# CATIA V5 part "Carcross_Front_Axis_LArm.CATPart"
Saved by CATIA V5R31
Part number: Carcross_Front_Axis_Larm
Bounding box of the stored display mesh (mm): x -35 to 226, y -610 to 0, z 0 to 365
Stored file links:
  R:\Din II\Pfinal\CAD\Carcross_Front_Axis_LArm.CATPart
  R:\Din II\Pfinal\CAD\Carcross_Front_Axis_HP.CATPart
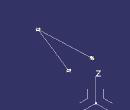
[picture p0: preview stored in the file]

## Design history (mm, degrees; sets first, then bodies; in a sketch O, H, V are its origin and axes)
AxisSystem1: origin (0, 0, 0), X (1, 0, 0), Y (0, 1, 0), Z (0, 0, 1)
Set1 "Front_Axis"
  Set2 "Left_wheel"
    Set3 "Upper_arm"
      Set4 "Upper_arm_C"
        Point1 "D": (-166, -99, 323.5), in AxisSystem1
        Point2 "E": (17, -546, 298.5), in AxisSystem1
        Point3 "F": (158, -124, 291.5), in AxisSystem1
        Line1: type PtPt, FirstPoint Point1, SecondPoint Point2
        Line2: type PtPt, FirstPoint Point3, SecondPoint Point2
        Plane1 "Upper_plane": type 3Points, Element1 Point1, Element2 Point2, Element3 Point3
      Join1 "Upper_arm": Elements (Line1; Line2)
    Set5 "IC_RollCenter"
      Intersect1 "IC_Line": ToIntersect2 Plane1
      Intersect2 "IC_point_YZ": ToIntersect1 YZ plane of AxisSystem1, ToIntersect2 Intersect1
      Line3: type PtPt, FirstPoint Intersect5, SecondPoint Intersect2
      Intersect3 "RollCenter": ToIntersect1 ZX plane of AxisSystem1, ToIntersect2 Plane2
      Project1 "Tierod_Projection": ToProject Join2, Support YZ plane of AxisSystem1
      Intersect4 "IC_Aux_ZX": ToIntersect1 Intersect1, ToIntersect2 ZX plane of AxisSystem1
      Plane2 "IC_Plane": type 1Line1Pt, RefPoint Intersect5, Line Intersect1
      Line4 "Tie_rod_IC": type Tangency, RefPoint vertex of Project1, Curve Project1, Start 0, End 8452.795
    Set6 "tie_rod"
      Set7 "tie_rod_C"
        Point4 "In": (-64, -105, 240.5), in AxisSystem1
        Point5 "Out": (-78, -588, 230), in AxisSystem1
        Line5: type PtPt, FirstPoint Point4, SecondPoint Point5
      Join2 "tierod": Elements Line5
    Set8 "Strut"
      Set9 "Strut_C"
        Point6 "Down": (3, -520, 148.5), in AxisSystem1
        Point7 "Up": (39, -166, 383.5), in AxisSystem1
        Line6: type PtPt, FirstPoint Point6, SecondPoint Point7
      Join3 "Strut": Elements Line6
    Set10 "Wheel"
      Point8 "Wheel_Center": (0, -800, 242.5), in AxisSystem1
      Line7: type PtDir, RefPoint Point8, Direction (0, 0, 1), Start -400, End 400
      Intersect5 "Wheel_Floor": ToIntersect1 Line7, ToIntersect2 XY plane of AxisSystem1
  Set11 "Right_Wheel"
    MultiSel1
Set12 "Lower_arm"
  Set13 "Lower_arm_C"
    Point9 "A": linked copy from another document
    Point10 "B": linked copy from another document
    Point11 "C": linked copy from another document
    Line8: linked copy from another document
    Line9: linked copy from another document
    Circle1 "inner_C": type CtrRad, Start 0, End 180, Center Point11, Support XY plane of AxisSystem1, Radius 10, FirstDirection (1, 0, 0)
    Circle2 "outter_C": type CtrRad, Start 0, End 180, Center Point11, Support XY plane of AxisSystem1, Radius 15 {= Circle1.Radius +5mm}, FirstDirection (1, 0, 0)
    Circle3 "inner_B": type CtrRad, Start 0, End 180, Center Point10, Support XY plane of AxisSystem1, Radius 10, FirstDirection (1, 0, 0)
    Circle4 "outter_B": type CtrRad, Start 0, End 180, Center Point10, Support XY plane of AxisSystem1, Radius 15 {= Circle3.Radius +5mm}, FirstDirection (1, 0, 0)
    Set14 "A_ring"
      Set15 "A_ring_C"
        Extrude1: Lim1 5, Lim2 5, Element1 Circle6
        Extrude2: Lim1 5, Lim2 5, Element1 Circle5
        Fill1: Boundary Circle6
        Offset1: Offset Fill1, Length 5
        Offset2: Offset Fill1, Length 5
        Fillet1: type BiTangent, Element1 Offset1, Element2 Extrude1, Radius 1
        Fillet2: type BiTangent, Element1 Fillet1, Element2 Offset2, Radius 1
        Fillet3: type BiTangent, Element1 Fillet2, Element2 Extrude2, Radius 1
        Circle5 "inner_A": type CtrRad, Start 0, End 180, Center Point9, Support YZ plane of AxisSystem1, Radius 10, FirstDirection (0, 1, 0)
        Circle6 "outter_A": type CtrRad, Start 0, End 180, Center Point9, Support YZ plane of AxisSystem1, Radius 15 {= Circle5.Radius +5mm}, FirstDirection (0, 1, 0)
      Join4 "A_ring": Elements Fillet3
    Set16 "A_ring_C"
      Extrude3: Element1 Circle8, Lim1 5, Lim2 5
      Extrude4: Element1 Circle7, Lim1 5, Lim2 5
      Fill2: Boundary Circle8
      Offset3: Offset Fill2, Length 5
      Offset4: Offset Fill2, Length 5
      Fillet4: type BiTangent, Element1 Offset3, Element2 Extrude3, Radius 1
      Fillet5: type BiTangent, Element1 Fillet4, Element2 Offset4, Radius 1
      Fillet6: type BiTangent, Element1 Fillet5, Element2 Extrude4, Radius 1
      Circle7 "inner_A": type CtrRad, Start 0, End 180, Center Point9, Support XY plane of AxisSystem1, Radius 10, FirstDirection (0, 1, 0)
      Circle8 "outter_A": type CtrRad, Start 0, End 180, Center Point9, Support XY plane of AxisSystem1, Radius 15 {= Circle7.Radius +5mm}, FirstDirection (0, 1, 0)
Body1 (main body)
